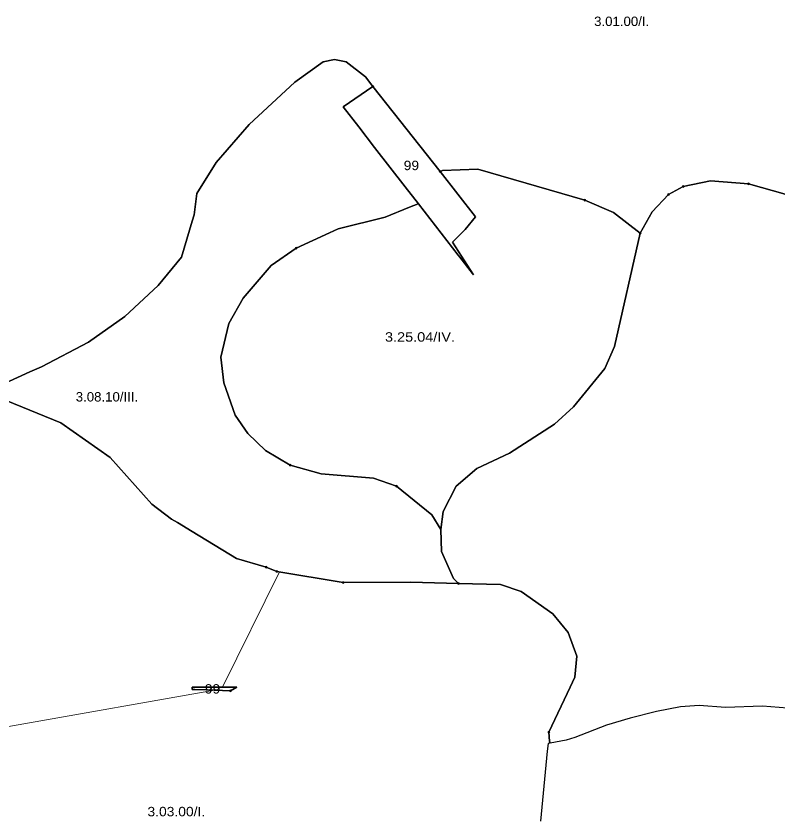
# Model space of a CAD drawing. Extents: x -650455 to -642254, y -1075222 to -1066610.
# Drawn here: x -647687 to -646878, y -1073142 to -1072287 of the extents above; entities that cross this region are included whole.
import ezdxf
from ezdxf.enums import TextEntityAlignment as Align

# ---------------------------------------------------------------- set-up
doc = ezdxf.new("R2010")
doc.units = 0
doc.header["$LTSCALE"] = 4
doc.header["$PDMODE"] = 32
doc.header["$PDSIZE"] = 2
for name, color, linetype, lineweight in [('1', 7, 'Continuous', 25), ('11', 7, 'Continuous', 13), ('13', 7, 'Continuous', 13), ('14', 7, 'Continuous', 13), ('16', 7, 'Continuous', 13)]:
    doc.layers.add(name, color=color, linetype=linetype, lineweight=lineweight)
doc.layers.add('2', color=7, linetype='Continuous')

msp = doc.modelspace()

# ---------------------------------------------------------------- linework, layer by layer
at = {"layer": '1'}
for points in [[(-647639.5, -1072719.001), (-647697.5, -1072695.5), (-647728.952, -1072689.256), (-647713.137, -1072683.505), (-647698.521, -1072676.851), (-647672.5, -1072665), (-647660, -1072659.5), (-647610, -1072633.501), (-647571.5, -1072606.001), (-647536, -1072573.001), (-647511.5, -1072543), (-647500, -1072504.667), (-647498, -1072498), (-647495, -1072475.501), (-647474.5, -1072442.501), (-647439.5, -1072402.001), (-647391, -1072357), (-647361, -1072335.5), (-647349, -1072333), (-647336.5, -1072335.5), (-647316, -1072351.5), (-647308, -1072361.501)], [(-646870, -1072476.001), (-646909, -1072465), (-646949.5, -1072462), (-646978.5, -1072468.001), (-646994, -1072476.501), (-647011.5, -1072495), (-647024, -1072517.5), (-647052.5, -1072495.501), (-647083, -1072482.5), (-647196.5, -1072449.5), (-647234, -1072451.001), (-647236.5, -1072452.001), (-647308, -1072361.501), (-647316, -1072351.5), (-647336.5, -1072335.5), (-647349, -1072333), (-647361, -1072335.5), (-647391, -1072357), (-647439.5, -1072402.001), (-647474.5, -1072442.501), (-647495, -1072475.501), (-647498, -1072498), (-647500, -1072504.667), (-647511.5, -1072543), (-647536, -1072573.001), (-647571.5, -1072606.001), (-647610, -1072633.501), (-647660, -1072659.5), (-647672.5, -1072665)], [(-647308, -1072361.501), (-647339.712, -1072383.178), (-647323.06, -1072404.651), (-647306.23, -1072426.351), (-647273.75, -1072468.221), (-647259.75, -1072486.28), (-647259.98, -1072486.34), (-647269, -1072490), (-647295, -1072500.501), (-647345, -1072513.001), (-647354, -1072517.001), (-647389.5, -1072533.5), (-647416, -1072552.001), (-647446, -1072586.5), (-647461, -1072613.501), (-647469.5, -1072649.501), (-647466.5, -1072676.5), (-647454.5, -1072711.001), (-647441, -1072730.501), (-647422, -1072748.5), (-647396, -1072764.001), (-647363, -1072773.5), (-647307.5, -1072778), (-647283, -1072786.5), (-647245.5, -1072817), (-647236, -1072832.501), (-647235, -1072856.001), (-647222.5, -1072884.501), (-647217, -1072890), (-647268, -1072888.501), (-647339.5, -1072889.001), (-647410, -1072877.001), (-647421.34, -1072872.531), (-647453, -1072863.5), (-647500, -1072834.548), (-647515.5, -1072825), (-647522, -1072821.5), (-647543, -1072805.5), (-647587, -1072756.001), (-647639.5, -1072719.001)], [(-647024, -1072517.5), (-647051.5, -1072638.001), (-647061.5, -1072661.501), (-647095, -1072702.001), (-647115, -1072720.5), (-647163, -1072751.501), (-647197.5, -1072767.501), (-647219.5, -1072786.5), (-647233.5, -1072813.5), (-647236, -1072832.501), (-647245.5, -1072817), (-647283, -1072786.5), (-647307.5, -1072778), (-647363, -1072773.5), (-647396, -1072764.001), (-647422, -1072748.5), (-647441, -1072730.501), (-647454.5, -1072711.001), (-647466.5, -1072676.5), (-647469.5, -1072649.501), (-647461, -1072613.501), (-647446, -1072586.5), (-647416, -1072552.001), (-647389.5, -1072533.5), (-647354, -1072517.001), (-647345, -1072513.001), (-647295, -1072500.501), (-647269, -1072490), (-647259.98, -1072486.34), (-647259.75, -1072486.28), (-647217.32, -1072540.99), (-647215.71, -1072543.071), (-647202.22, -1072560.471), (-647201.29, -1072561.671), (-647223.5, -1072527), (-647210, -1072513.5), (-647199, -1072500.001), (-647236.5, -1072452.001), (-647234, -1072451.001), (-647196.5, -1072449.5)], [(-647196.5, -1072449.5), (-647083, -1072482.5), (-647052.5, -1072495.501), (-647024, -1072517.5)], [(-647197.5, -1072767.501), (-647163, -1072751.501), (-647115, -1072720.5), (-647095, -1072702.001), (-647061.5, -1072661.501), (-647051.5, -1072638.001), (-647024, -1072517.5), (-647011.5, -1072495), (-646994, -1072476.501), (-646978.5, -1072468.001), (-646949.5, -1072462), (-646909, -1072465), (-646870, -1072476.001), (-646796, -1072525.5), (-646755, -1072562), (-646671, -1072656.5), (-646615.5, -1072728.5), (-646581.5, -1072768.5), (-646545.5, -1072791.001), (-646519.5, -1072800.501)], [(-647672.5, -1072665), (-647698.521, -1072676.851)], [(-647904.5, -1073148.001), (-647889.5, -1073048.5), (-647885.418, -1073000), (-647881, -1072947.5), (-647868, -1072828.501), (-647861.5, -1072813), (-647845.5, -1072785), (-647801.5, -1072733.5), (-647763.5, -1072702.001), (-647731, -1072690.001), (-647728.952, -1072689.256), (-647697.5, -1072695.5), (-647639.5, -1072719.001), (-647587, -1072756.001), (-647543, -1072805.5), (-647522, -1072821.5), (-647515.5, -1072825), (-647500, -1072834.548), (-647453, -1072863.5), (-647421.34, -1072872.531), (-647410, -1072877.001), (-647339.5, -1072889.001)], [(-646867.497, -1073022.31), (-646894.212, -1073020.321), (-646933.434, -1073021.742), (-646961.287, -1073019.609), (-646981.181, -1073021.173), (-647006.761, -1073025.862), (-647034.898, -1073032.967), (-647060.05, -1073040.642), (-647093.445, -1073053.573), (-647102.824, -1073056.274), (-647119.798, -1073059.69), (-647120.5, -1073057.5), (-647121, -1073048), (-647098.436, -1073000), (-647093.5, -1072989.501), (-647091.5, -1072967), (-647100.5, -1072942.001), (-647117, -1072922.001), (-647150.5, -1072898.5), (-647172.5, -1072891), (-647217, -1072890), (-647222.5, -1072884.501), (-647235, -1072856.001), (-647236, -1072832.501), (-647233.5, -1072813.5), (-647219.5, -1072786.5), (-647197.5, -1072767.501)], [(-647339.5, -1072889.001), (-647268, -1072888.501), (-647217, -1072890)], [(-647217, -1072890), (-647172.5, -1072891), (-647150.5, -1072898.5), (-647117, -1072922.001), (-647100.5, -1072942.001), (-647091.5, -1072967), (-647093.5, -1072989.501), (-647098.436, -1073000), (-647121, -1073048), (-647120.5, -1073057.5), (-647119.798, -1073059.69), (-647121.913, -1073060.116), (-647122.941, -1073068.189), (-647130.088, -1073142.652)]]:
    msp.add_lwpolyline(points, dxfattribs=at)
for points in [[(-647236.5, -1072452.001), (-647199, -1072500.001), (-647210, -1072513.5), (-647223.5, -1072527), (-647201.29, -1072561.671), (-647202.22, -1072560.471), (-647215.71, -1072543.071), (-647217.32, -1072540.99), (-647259.75, -1072486.28), (-647273.75, -1072468.221), (-647306.23, -1072426.351), (-647323.06, -1072404.651), (-647339.712, -1072383.178), (-647308, -1072361.501)], [(-647452.469, -1073000), (-647459.21, -1073004.071), (-647485.29, -1073003.08), (-647497.2, -1073002.63), (-647500, -1073002.544), (-647500.13, -1073002.54), (-647500.097, -1073000), (-647500, -1073000)], [(-647452.469, -1073000), (-647500, -1073000), (-647500.097, -1073000), (-647500.13, -1073002.54), (-647500, -1073002.544), (-647497.2, -1073002.63), (-647485.29, -1073003.08), (-647459.21, -1073004.071)]]:
    msp.add_lwpolyline(points, close=True, dxfattribs=at)
at = {"layer": '11'}
for p, q in [((-646978.5, -1072468.001), (-646994, -1072476.501)), ((-646870, -1072476.001), (-646909, -1072465)), ((-647410, -1072877.001), (-647421.34, -1072872.531))]:
    msp.add_line(p, q, dxfattribs=at)
for points in [[(-647845.5, -1072785), (-647801.5, -1072733.5), (-647763.5, -1072702.001), (-647731, -1072690.001), (-647728.952, -1072689.256), (-647713.137, -1072683.505), (-647698.521, -1072676.851), (-647672.5, -1072665), (-647660, -1072659.5), (-647610, -1072633.501), (-647571.5, -1072606.001), (-647536, -1072573.001), (-647511.5, -1072543), (-647500, -1072504.667), (-647498, -1072498), (-647495, -1072475.501), (-647474.5, -1072442.501), (-647439.5, -1072402.001), (-647391, -1072357), (-647361, -1072335.5), (-647349, -1072333), (-647336.5, -1072335.5), (-647316, -1072351.5), (-647308, -1072361.501)], [(-647308, -1072361.501), (-647236.5, -1072452.001), (-647234, -1072451.001), (-647196.5, -1072449.5), (-647083, -1072482.5)], [(-647083, -1072482.5), (-647052.5, -1072495.501), (-647024, -1072517.5), (-647011.5, -1072495), (-646994, -1072476.501), (-646978.5, -1072468.001), (-646949.5, -1072462), (-646909, -1072465), (-646870, -1072476.001), (-646796, -1072525.5)], [(-646909, -1072465), (-646949.5, -1072462), (-646978.5, -1072468.001)], [(-646994, -1072476.501), (-647011.5, -1072495), (-647024, -1072517.5)], [(-647024, -1072517.5), (-647051.5, -1072638.001), (-647061.5, -1072661.501), (-647095, -1072702.001), (-647115, -1072720.5), (-647163, -1072751.501), (-647197.5, -1072767.501), (-647219.5, -1072786.5), (-647233.5, -1072813.5), (-647236, -1072832.501), (-647235, -1072856.001), (-647222.5, -1072884.501), (-647217, -1072890)], [(-647421.34, -1072872.531), (-647453, -1072863.5), (-647500, -1072834.548), (-647515.5, -1072825), (-647522, -1072821.5), (-647543, -1072805.5), (-647587, -1072756.001), (-647639.5, -1072719.001), (-647697.5, -1072695.5), (-647728.952, -1072689.256), (-647731, -1072690.001), (-647763.5, -1072702.001), (-647801.5, -1072733.5), (-647845.5, -1072785), (-647861.5, -1072813), (-647868, -1072828.501), (-647881, -1072947.5), (-647885.418, -1073000), (-647889.5, -1073048.5)], [(-647339.5, -1072889.001), (-647407.174, -1072877.482), (-647467.805, -1073000), (-647452.469, -1073000), (-647459.21, -1073004.071), (-647476.435, -1073003.416), (-647893.795, -1073076.991), (-647904.5, -1073148.001), (-647917.5, -1073209.501), (-647919.5, -1073256), (-647914.5, -1073287.5), (-647902, -1073313.501), (-647885, -1073332.5), (-647865, -1073347.001), (-647852.5, -1073352.5), (-647735.5, -1073384), (-647648, -1073415.501), (-647589.5, -1073433)], [(-647476.435, -1073003.416), (-647485.29, -1073003.08), (-647497.2, -1073002.63), (-647500, -1073002.544), (-647500.13, -1073002.54), (-647500.097, -1073000), (-647500, -1073000), (-647467.805, -1073000), (-647407.174, -1072877.482), (-647410, -1072877.001)], [(-647130.088, -1073142.652), (-647122.941, -1073068.189), (-647121.913, -1073060.116), (-647119.798, -1073059.69), (-647120.5, -1073057.5), (-647121, -1073048), (-647098.436, -1073000), (-647093.5, -1072989.501), (-647091.5, -1072967), (-647100.5, -1072942.001), (-647117, -1072922.001), (-647150.5, -1072898.5), (-647172.5, -1072891), (-647217, -1072890), (-647268, -1072888.501), (-647339.5, -1072889.001)], [(-647217, -1072890), (-647172.5, -1072891), (-647150.5, -1072898.5), (-647117, -1072922.001), (-647100.5, -1072942.001), (-647091.5, -1072967), (-647093.5, -1072989.501), (-647098.436, -1073000), (-647121, -1073048)], [(-647889.5, -1073048.5), (-647893.795, -1073076.991), (-647476.435, -1073003.416)], [(-647121, -1073048), (-647120.5, -1073057.5), (-647119.798, -1073059.69), (-647102.824, -1073056.274), (-647093.445, -1073053.573), (-647060.05, -1073040.642), (-647034.898, -1073032.967), (-647006.761, -1073025.862), (-646981.181, -1073021.173), (-646961.287, -1073019.609), (-646933.434, -1073021.742), (-646894.212, -1073020.321), (-646867.497, -1073022.31)]]:
    msp.add_lwpolyline(points, dxfattribs=at)
for p in [(-647308, -1072361.501), (-646909, -1072465), (-646978.5, -1072468.001), (-646994, -1072476.501), (-647083, -1072482.5), (-647024, -1072517.5), (-647421.34, -1072872.531), (-647410, -1072877.001), (-647339.5, -1072889.001), (-647217, -1072890), (-647121, -1073048)]:
    msp.add_point(p, dxfattribs=at)
at = {"layer": '13'}
for points in [[(-647308, -1072361.501), (-647316, -1072351.5), (-647336.5, -1072335.5), (-647349, -1072333), (-647361, -1072335.5), (-647391, -1072357), (-647439.5, -1072402.001), (-647474.5, -1072442.501), (-647495, -1072475.501), (-647498, -1072498), (-647500, -1072504.667), (-647511.5, -1072543), (-647536, -1072573.001), (-647571.5, -1072606.001), (-647610, -1072633.501), (-647660, -1072659.5), (-647672.5, -1072665), (-647698.521, -1072676.851), (-647713.137, -1072683.505), (-647728.952, -1072689.256), (-647697.5, -1072695.5), (-647639.5, -1072719.001), (-647587, -1072756.001)], [(-647389.5, -1072533.5), (-647354, -1072517.001), (-647345, -1072513.001), (-647295, -1072500.501), (-647269, -1072490), (-647259.98, -1072486.34), (-647259.75, -1072486.28), (-647273.75, -1072468.221), (-647306.23, -1072426.351), (-647323.06, -1072404.651), (-647339.712, -1072383.178), (-647308, -1072361.501)], [(-647283, -1072786.5), (-647307.5, -1072778), (-647363, -1072773.5), (-647396, -1072764.001), (-647422, -1072748.5), (-647441, -1072730.501), (-647454.5, -1072711.001), (-647466.5, -1072676.5), (-647469.5, -1072649.501), (-647461, -1072613.501), (-647446, -1072586.5), (-647416, -1072552.001), (-647389.5, -1072533.5)], [(-647587, -1072756.001), (-647543, -1072805.5), (-647522, -1072821.5), (-647515.5, -1072825), (-647500, -1072834.548), (-647453, -1072863.5), (-647421.34, -1072872.531), (-647410, -1072877.001), (-647339.5, -1072889.001), (-647268, -1072888.501), (-647217, -1072890), (-647222.5, -1072884.501), (-647235, -1072856.001), (-647236, -1072832.501), (-647245.5, -1072817), (-647283, -1072786.5)]]:
    msp.add_lwpolyline(points, dxfattribs=at)
for p in [(-647308, -1072361.501), (-647389.5, -1072533.5), (-647283, -1072786.5)]:
    msp.add_point(p, dxfattribs=at)
at = {"layer": '14'}
for points in [[(-647236.5, -1072452.001), (-647199, -1072500.001), (-647210, -1072513.5), (-647223.5, -1072527), (-647201.29, -1072561.671), (-647202.22, -1072560.471), (-647215.71, -1072543.071), (-647217.32, -1072540.99), (-647259.75, -1072486.28), (-647259.98, -1072486.34), (-647269, -1072490), (-647295, -1072500.501), (-647345, -1072513.001), (-647354, -1072517.001), (-647389.5, -1072533.5), (-647416, -1072552.001), (-647446, -1072586.5), (-647461, -1072613.501), (-647469.5, -1072649.501), (-647466.5, -1072676.5), (-647454.5, -1072711.001), (-647441, -1072730.501), (-647422, -1072748.5), (-647396, -1072764.001)], [(-647283, -1072786.5), (-647245.5, -1072817), (-647236, -1072832.501), (-647233.5, -1072813.5), (-647219.5, -1072786.5), (-647197.5, -1072767.501), (-647163, -1072751.501), (-647115, -1072720.5), (-647095, -1072702.001), (-647061.5, -1072661.501), (-647051.5, -1072638.001), (-647024, -1072517.5), (-647052.5, -1072495.501), (-647083, -1072482.5), (-647196.5, -1072449.5), (-647234, -1072451.001), (-647236.5, -1072452.001)], [(-647396, -1072764.001), (-647363, -1072773.5), (-647307.5, -1072778), (-647283, -1072786.5)]]:
    msp.add_lwpolyline(points, dxfattribs=at)
for p in [(-647236.5, -1072452.001), (-647396, -1072764.001), (-647283, -1072786.5)]:
    msp.add_point(p, dxfattribs=at)
at = {"layer": '16'}
for points in [[(-647217.32, -1072540.99), (-647215.71, -1072543.071), (-647202.22, -1072560.471), (-647201.29, -1072561.671), (-647223.5, -1072527), (-647210, -1072513.5), (-647199, -1072500.001), (-647236.5, -1072452.001), (-647308, -1072361.501), (-647339.712, -1072383.178), (-647323.06, -1072404.651), (-647306.23, -1072426.351), (-647273.75, -1072468.221), (-647259.75, -1072486.28)], [(-647459.21, -1073004.071), (-647452.469, -1073000), (-647467.805, -1073000), (-647500, -1073000), (-647500.097, -1073000), (-647500.13, -1073002.54), (-647500, -1073002.544), (-647497.2, -1073002.63), (-647485.29, -1073003.08)]]:
    msp.add_lwpolyline(points, close=True, dxfattribs=at)
msp.add_point((-647459.21, -1073004.071), dxfattribs=at)

# ---------------------------------------------------------------- texts
at = {"layer": '2'}
for s, width, p in [('3.01.00/I.', 1.05, (-647043.757, -1072297.321)), ('99', 1.1, (-647267.127, -1072450.514)), ('3.25.04/IV.', 1.15, (-647257.99, -1072632.827)), ('3.08.10/III.', 1.05, (-647590.541, -1072696.467)), ('99', 1.1, (-647478.431, -1073006.911)), ('3.03.00/I.', 1.1, (-647516.849, -1073137.354))]:
    msp.add_text(s, height=10, dxfattribs=dict(at, width=width)).set_placement(p, align=Align.CENTER)

doc.saveas('drawing.dxf')
